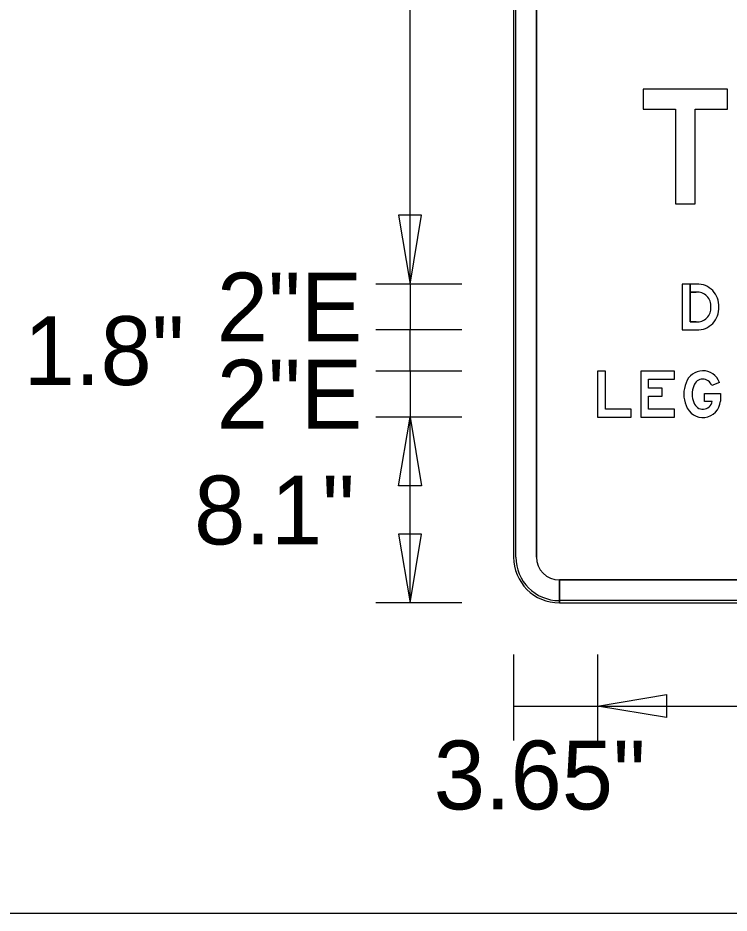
# Model space of a CAD drawing. Extents: x 17890628 to 17890844, y 17897693 to 17898031.
# Drawn here: x 17890803.98 to 17890813.01, y 17897934.95 to 17897946.34 of the extents above; entities that cross this region are included whole.
import ezdxf

# ---------------------------------------------------------------- set-up
doc = ezdxf.new("R2010")
doc.units = 0
for name, color, linetype in [('GSBWFill', 7, 'Continuous'), ('GSColorFill', 7, 'Continuous'), ('GSDims', 7, 'Continuous'), ('GSOutline', 7, 'Continuous'), ('SheetLinesMisc2_dp', 7, 'Continuous')]:
    doc.layers.add(name, color=color, linetype=linetype)

msp = doc.modelspace()

# ---------------------------------------------------------------- linework, layer by layer
at = {"layer": 'GSBWFill'}
for p, q in [((17890810.271, 17897952.314), (17890810.271, 17897939.481)), ((17890810.563, 17897939.481), (17890810.563, 17897952.314)), ((17890812.888, 17897941.701), (17890812.79, 17897941.663)), ((17890810.855, 17897938.897), (17890810.855, 17897939.189)), ((17890823.688, 17897939.189), (17890810.858, 17897939.189)), ((17890810.858, 17897939.189), (17890810.858, 17897938.897)), ((17890810.858, 17897938.897), (17890823.688, 17897938.897))]:
    msp.add_line(p, q, dxfattribs=at)
for points in [[(17890811.921, 17897945.176), (17890812.33, 17897945.176), (17890812.33, 17897943.972), (17890812.581, 17897943.972), (17890812.581, 17897945.176), (17890812.991, 17897945.176), (17890812.991, 17897945.431), (17890811.921, 17897945.431)], [(17890811.767, 17897941.26), (17890811.767, 17897941.362), (17890811.439, 17897941.362), (17890811.439, 17897941.843), (17890811.339, 17897941.843), (17890811.339, 17897941.26)], [(17890812.316, 17897941.362), (17890811.988, 17897941.362), (17890811.988, 17897941.525), (17890812.162, 17897941.525), (17890812.162, 17897941.627), (17890811.988, 17897941.627), (17890811.988, 17897941.741), (17890812.316, 17897941.741), (17890812.316, 17897941.843), (17890811.888, 17897941.843), (17890811.888, 17897941.26), (17890812.316, 17897941.26)]]:
    msp.add_lwpolyline(points, close=True, dxfattribs=at)
for points in [[(17890812.592, 17897942.47), (17890812.517, 17897942.47), (17890812.517, 17897942.952), (17890812.416, 17897942.952), (17890812.416, 17897942.368), (17890812.6, 17897942.368)], [(17890812.6, 17897942.952), (17890812.517, 17897942.952), (17890812.517, 17897942.85), (17890812.592, 17897942.85)], [(17890812.795, 17897941.459), (17890812.697, 17897941.459), (17890812.697, 17897941.562), (17890812.902, 17897941.562), (17890812.902, 17897941.462)]]:
    msp.add_lwpolyline(points, dxfattribs=at)
for radius in [0.583, 0.292]:
    msp.add_arc((17890810.855, 17897939.481), radius, 180, 270, dxfattribs=at)
for centre, major_axis, start_param, end_param in [((17890812.607, 17897942.673), (0, 0.279), 4.66648, 6.308552), ((17890812.603, 17897942.669), (0, 0.181), 4.662785, 6.345315), ((17890812.603, 17897942.651), (0, 0.181), 3.079463, 4.761992), ((17890812.607, 17897942.647), (0, 0.279), 3.116226, 4.758298), ((17890812.677, 17897941.62), (0, 0.229), 5.073935, 7.515122), ((17890812.792, 17897941.554), (0, 0.361), 1.165718, 1.57629), ((17890812.806, 17897941.551), (0, 0.268), 1.157766, 1.568975), ((17890812.678, 17897941.623), (0, 0.121), 5.049811, 7.549107), ((17890812.792, 17897941.55), (0, 0.361), 1.565303, 1.975874), ((17890812.806, 17897941.552), (0, 0.268), 1.572617, 1.983827), ((17890812.677, 17897941.484), (0, 0.229), 1.909656, 4.617417), ((17890812.678, 17897941.481), (0, 0.121), 1.875671, 4.536274)]:
    msp.add_ellipse(centre, major_axis=major_axis, ratio=0.985, start_param=start_param, end_param=end_param, dxfattribs=at)
at = {"layer": 'GSColorFill'}
for p, q in [((17890810.271, 17897952.314), (17890810.271, 17897939.481)), ((17890810.271, 17897952.314), (17890810.271, 17897939.481)), ((17890810.271, 17897952.314), (17890810.271, 17897939.481)), ((17890810.301, 17897939.481), (17890810.301, 17897952.314)), ((17890810.563, 17897939.481), (17890810.563, 17897952.314)), ((17890812.888, 17897941.701), (17890812.79, 17897941.663)), ((17890810.855, 17897938.897), (17890810.855, 17897939.189)), ((17890823.688, 17897939.189), (17890810.858, 17897939.189)), ((17890810.858, 17897939.189), (17890810.858, 17897938.897)), ((17890810.855, 17897938.897), (17890810.855, 17897938.927)), ((17890823.688, 17897938.927), (17890810.855, 17897938.927)), ((17890810.855, 17897938.927), (17890810.855, 17897938.897)), ((17890810.855, 17897938.897), (17890823.688, 17897938.897)), ((17890810.855, 17897938.897), (17890823.688, 17897938.897)), ((17890810.858, 17897938.897), (17890823.688, 17897938.897))]:
    msp.add_line(p, q, dxfattribs=at)
for points in [[(17890811.921, 17897945.176), (17890812.33, 17897945.176), (17890812.33, 17897943.972), (17890812.581, 17897943.972), (17890812.581, 17897945.176), (17890812.991, 17897945.176), (17890812.991, 17897945.431), (17890811.921, 17897945.431)], [(17890811.767, 17897941.26), (17890811.767, 17897941.362), (17890811.439, 17897941.362), (17890811.439, 17897941.843), (17890811.339, 17897941.843), (17890811.339, 17897941.26)], [(17890812.316, 17897941.362), (17890811.988, 17897941.362), (17890811.988, 17897941.525), (17890812.162, 17897941.525), (17890812.162, 17897941.627), (17890811.988, 17897941.627), (17890811.988, 17897941.741), (17890812.316, 17897941.741), (17890812.316, 17897941.843), (17890811.888, 17897941.843), (17890811.888, 17897941.26), (17890812.316, 17897941.26)]]:
    msp.add_lwpolyline(points, close=True, dxfattribs=at)
for points in [[(17890812.592, 17897942.47), (17890812.517, 17897942.47), (17890812.517, 17897942.952), (17890812.416, 17897942.952), (17890812.416, 17897942.368), (17890812.6, 17897942.368)], [(17890812.6, 17897942.952), (17890812.517, 17897942.952), (17890812.517, 17897942.85), (17890812.592, 17897942.85)], [(17890812.795, 17897941.459), (17890812.697, 17897941.459), (17890812.697, 17897941.562), (17890812.902, 17897941.562), (17890812.902, 17897941.462)]]:
    msp.add_lwpolyline(points, dxfattribs=at)
for radius in [0.583, 0.583, 0.583, 0.554, 0.292]:
    msp.add_arc((17890810.855, 17897939.481), radius, 180, 270, dxfattribs=at)
for centre, major_axis, start_param, end_param in [((17890812.607, 17897942.673), (0, 0.279), 4.66648, 6.308552), ((17890812.603, 17897942.669), (0, 0.181), 4.662785, 6.345315), ((17890812.603, 17897942.651), (0, 0.181), 3.079463, 4.761992), ((17890812.607, 17897942.647), (0, 0.279), 3.116226, 4.758298), ((17890812.677, 17897941.62), (0, 0.229), 5.073935, 7.515122), ((17890812.792, 17897941.554), (0, 0.361), 1.165718, 1.57629), ((17890812.806, 17897941.551), (0, 0.268), 1.157766, 1.568975), ((17890812.678, 17897941.623), (0, 0.121), 5.049811, 7.549107), ((17890812.792, 17897941.55), (0, 0.361), 1.565303, 1.975874), ((17890812.806, 17897941.552), (0, 0.268), 1.572617, 1.983827), ((17890812.677, 17897941.484), (0, 0.229), 1.909656, 4.617417), ((17890812.678, 17897941.481), (0, 0.121), 1.875671, 4.536274)]:
    msp.add_ellipse(centre, major_axis=major_axis, ratio=0.985, start_param=start_param, end_param=end_param, dxfattribs=at)
at = {"layer": 'GSDims'}
for p, q in [((17890808.959, 17897942.952), (17890808.959, 17897952.897)), ((17890809.615, 17897942.952), (17890808.521, 17897942.952)), ((17890809.615, 17897942.952), (17890808.521, 17897942.952)), ((17890808.959, 17897942.952), (17890808.959, 17897942.368)), ((17890809.615, 17897942.368), (17890808.521, 17897942.368)), ((17890809.615, 17897942.368), (17890808.521, 17897942.368)), ((17890808.959, 17897941.843), (17890808.959, 17897942.368)), ((17890809.615, 17897941.843), (17890808.521, 17897941.843)), ((17890809.615, 17897941.843), (17890808.521, 17897941.843)), ((17890808.959, 17897941.843), (17890808.959, 17897941.26)), ((17890809.615, 17897941.26), (17890808.521, 17897941.26)), ((17890809.615, 17897941.26), (17890808.521, 17897941.26)), ((17890808.959, 17897938.897), (17890808.959, 17897941.26)), ((17890809.615, 17897938.897), (17890808.521, 17897938.897)), ((17890810.271, 17897938.241), (17890810.271, 17897937.147)), ((17890811.339, 17897938.241), (17890811.339, 17897937.147)), ((17890811.339, 17897938.241), (17890811.339, 17897937.147)), ((17890810.271, 17897937.585), (17890811.339, 17897937.585)), ((17890811.339, 17897937.585), (17890823.204, 17897937.585))]:
    msp.add_line(p, q, dxfattribs=at)
for points in [[(17890808.959, 17897942.952), (17890809.105, 17897943.827), (17890808.813, 17897943.827)], [(17890808.959, 17897941.26), (17890809.105, 17897940.385), (17890808.813, 17897940.385)], [(17890808.959, 17897938.897), (17890809.105, 17897939.772), (17890808.813, 17897939.772)], [(17890811.339, 17897937.585), (17890812.214, 17897937.731), (17890812.214, 17897937.439)]]:
    msp.add_lwpolyline(points, close=True, dxfattribs=at)
at = {"layer": 'GSOutline'}
for p, q in [((17890810.271, 17897952.314), (17890810.271, 17897939.481)), ((17890810.563, 17897952.314), (17890810.563, 17897939.481)), ((17890812.517, 17897942.47), (17890812.592, 17897942.47)), ((17890812.416, 17897942.368), (17890812.6, 17897942.368)), ((17890812.888, 17897941.701), (17890812.79, 17897941.663)), ((17890810.855, 17897939.189), (17890823.688, 17897939.189)), ((17890810.855, 17897938.897), (17890823.688, 17897938.897))]:
    msp.add_line(p, q, dxfattribs=at)
for points in [[(17890811.921, 17897945.176), (17890812.33, 17897945.176), (17890812.33, 17897943.972), (17890812.581, 17897943.972), (17890812.581, 17897945.176), (17890812.991, 17897945.176), (17890812.991, 17897945.431), (17890811.921, 17897945.431)], [(17890811.767, 17897941.26), (17890811.767, 17897941.362), (17890811.439, 17897941.362), (17890811.439, 17897941.843), (17890811.339, 17897941.843), (17890811.339, 17897941.26)], [(17890812.316, 17897941.362), (17890811.988, 17897941.362), (17890811.988, 17897941.525), (17890812.162, 17897941.525), (17890812.162, 17897941.627), (17890811.988, 17897941.627), (17890811.988, 17897941.741), (17890812.316, 17897941.741), (17890812.316, 17897941.843), (17890811.888, 17897941.843), (17890811.888, 17897941.26), (17890812.316, 17897941.26)]]:
    msp.add_lwpolyline(points, close=True, dxfattribs=at)
for points in [[(17890812.6, 17897942.952), (17890812.416, 17897942.952), (17890812.416, 17897942.368)], [(17890812.592, 17897942.85), (17890812.517, 17897942.85), (17890812.517, 17897942.47)], [(17890812.795, 17897941.459), (17890812.697, 17897941.459), (17890812.697, 17897941.562), (17890812.902, 17897941.562), (17890812.902, 17897941.462)]]:
    msp.add_lwpolyline(points, dxfattribs=at)
for radius in [0.583, 0.292]:
    msp.add_arc((17890810.855, 17897939.481), radius, 180, 270, dxfattribs=at)
for centre, major_axis, start_param, end_param in [((17890812.607, 17897942.673), (0, 0.279), 4.66648, 6.308552), ((17890812.603, 17897942.669), (0, 0.181), 4.662786, 6.345315), ((17890812.603, 17897942.651), (0, 0.181), 3.079463, 4.761992), ((17890812.607, 17897942.647), (0, 0.279), 3.116226, 4.758298), ((17890812.677, 17897941.62), (0, 0.229), 5.073935, 7.515122), ((17890812.792, 17897941.554), (0, 0.361), 1.165718, 1.57629), ((17890812.806, 17897941.551), (0, 0.268), 1.157766, 1.568975), ((17890812.678, 17897941.623), (0, 0.121), 5.049811, 7.549107), ((17890812.792, 17897941.55), (0, 0.361), 1.565303, 1.975874), ((17890812.806, 17897941.552), (0, 0.268), 1.572617, 1.983827), ((17890812.677, 17897941.484), (0, 0.229), 1.909656, 4.617417), ((17890812.678, 17897941.481), (0, 0.121), 1.875671, 4.536274)]:
    msp.add_ellipse(centre, major_axis=major_axis, ratio=0.985, start_param=start_param, end_param=end_param, dxfattribs=at)
at = {"layer": 'SheetLinesMisc2_dp'}
msp.add_line((17890793.11, 17897934.953), (17890838.594, 17897934.953), dxfattribs=at)

# ---------------------------------------------------------------- texts
at = {"layer": 'GSDims'}
for s, p in [('2"E', (17890806.503, 17897942.222)), ('1.8"', (17890804.049, 17897941.668)), ('2"E', (17890806.503, 17897941.114)), ('8.1"', (17890806.214, 17897939.641)), ('3.65"', (17890809.259, 17897936.272))]:
    msp.add_text(s, height=0.875, dxfattribs=at).set_placement(p)

doc.saveas('drawing.dxf')
